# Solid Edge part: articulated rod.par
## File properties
Author: Robert a Rhodes jr
Template: Normal.par
Last saved by: Cadcim
Revision: 10
Application: Solid Edge
Accuracy: 0.99
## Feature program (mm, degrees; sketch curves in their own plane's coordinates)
pattern "unnamed Pattern 1"
pattern "unnamed Pattern 2"
Other named dimensions: "Hole_2": Diameter = 15 mm
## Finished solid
Body 1: solid body, 26 faces, 56 edges, 32 vertices.
  Faces by surface: plane 14, cylinder 12
  Edges by curve: circle 28, line 28
Bounding box of the edges (mm): 207.500 x 35.000 x 42.000, from (-101, -17.5, -21) to (106.5, 17.5, 21).
Cylindrical faces by radius (mm): R6.35 x4, R7.5 x1, R12 x2, R17.5 x1, R24 x4
Planar faces by outward normal: +y 3, +z 4, -y 3, -z 4
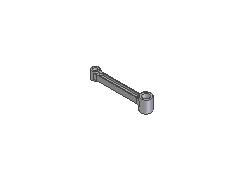
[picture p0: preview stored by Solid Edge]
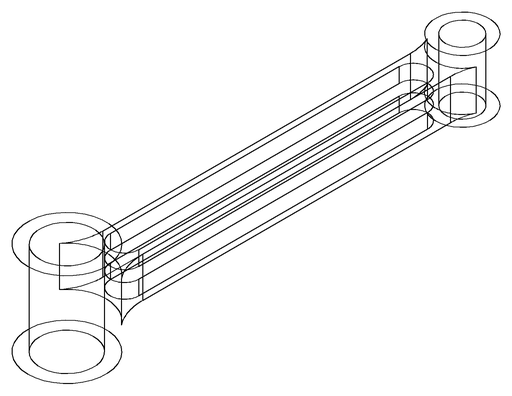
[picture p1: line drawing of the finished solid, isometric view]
